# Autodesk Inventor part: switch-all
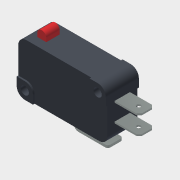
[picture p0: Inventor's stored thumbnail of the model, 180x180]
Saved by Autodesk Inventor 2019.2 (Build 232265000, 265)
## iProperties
Shininess: 64.0
Length Units: 11269
Angle Units: 11279
Time Units: 11290
Mass Units: 11286
Length Display Precision: 3
Angle Display Precision: 2
Compacted: True
Part Number: switch-all
Document SubType Name: Modeling
Created: 2003-07
Designer: garding
Manufacturer: Standard
Standards Organization: Custom
Material: Default
Density: 1 g/cm^3
Appearance: Dark Gray
Density: 0.0
Volumn: 0.0
Area: 0.0
PropertySet Name: Model Information
Control State: 0
Master: False
Checked Out: False
Author: garding
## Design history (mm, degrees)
sketch "Sketch1"
  geometry: L1 (-13.9, 7.95)-(13.9, 7.95); L2 (13.9, 7.95)-(13.9, -7.95); L3 (13.9, -7.95)-(-13.9, -7.95); L4 (-13.9, -7.95)-(-13.9, 7.95); 3 further points
  constraints: 8 end point, 2 midpoint, 2 parallel, 1 horizontal, 1 horizontal alignment, 1 perpendicular, 1 vertical alignment
  dimensions: "d0" = 27.8 distance of L1.start L1.end; "d1" = 15.9 distance of L1.end L2.end
extrude "Extrusion1" new body sketch "Sketch1" stored distance "d2" = 10.3; taper "d3" = 0 deg
fillet "Fillet1" dims "d4" = 2.54
sketch "Sketch2"
  geometry: L1 (0.837, 7.25)-(3.637, 7.25); L2 (3.637, 7.25)-(3.637, 3.05); L3 (3.637, 3.05)-(0.837, 3.05); L4 (0.837, 3.05)-(0.837, 7.25); L5 (0, 0)-(0, 10.3) reference; 2 further points
  constraints: 8 end point, 2 midpoint, 2 parallel, 1 horizontal, 1 horizontal alignment, 1 perpendicular
  dimensions: "d66" = 4.2 distance of L1.end L2.end; "d67" = 2.8 distance of L1.start L1.end
extrude "Extrusion2" join sketch "Sketch2" distance "d5" = 2.54; taper "d6" = 0 deg
fillet "Fillet2" dims "d7" = 1.4
sketch "Sketch3"
  geometry: L1 (-11.36, -7.95)-(11.36, -7.95) reference; L2 (11.754, -10.998)-(1.086, -10.998); L3 (1.086, -10.998)-(1.086, -7.95); L4 (-13.9, 5.41)-(-13.9, -5.41) reference; L5 (11.754, -10.998)-(11.754, -10.236); L6 (11.754, -10.236)-(1.848, -10.236); L7 (1.848, -10.236)-(1.848, -7.95)
  constraints: 10 end point, 2 parallel, 2 perpendicular, 2 point on line
  dimensions: "d10" = 10.668 distance of L2.start L2.end; "d12" = 3.048 distance of L2.end L3.end; "d13" = 14.986 distance between parallel lines of L4 L3; "d14" = 0.762 distance between parallel lines of L2 L6; "d15" = 0.762 distance between parallel lines of L3 L7 (= d14)
extrude "pin1" join sketch "Sketch3" stored distance "d16" = 4.7498; taper "d17" = 0 deg
fillet "pin1 Fillet3" dims "d18" = 0.762, "d19" = 1.524
sketch "Sketch4"
  geometry: L1 (9.144, 0.762)-(9.144, 3.988) reference; 2 further points
  constraints: 1 horizontal alignment, 1 midpoint
hole "pin1 Hole1" sketch "Sketch4" at (6.536, 2.375) diameter "d20" = 1.27; stored, may be unused: countersink angle "d24" = 82 deg, drill point angle "d26" = 118 deg; dims "d21" = 12.7, "d22" = 9.525, "d23" = 6.35, "d25" = 19.05
sketch "Sketch5"
  geometry: A1 r 2.54 centre (-11.36, -5.41) between (-13.9, -5.41) and (-11.36, -7.95) reference; A2 r 2.54 centre (11.36, 5.41) between (13.9, 5.41) and (11.36, 7.95) reference
hole "Hole2" sketch "Sketch5" at (-11.36, -5.41), (11.36, 5.41) diameter "d27" = 2.54; stored, may be unused: countersink angle "d31" = 82 deg, drill point angle "d33" = 118 deg; dims "d28" = 12.7, "d29" = 9.525, "d30" = 6.35, "d32" = 19.05
sketch "Sketch6"
  geometry: L1 (0, 0)-(0, 10.82) reference; L2 (-10.3, 10.82)-(0, 10.82) reference; L3 (-10.3, 10.82)-(-10.3, 0) reference; L4 (-7.525, 8.458)-(-2.775, 8.458); L5 (-2.775, 8.458)-(-2.775, 7.95); L6 (-2.775, 7.95)-(-7.525, 7.95); L7 (-7.525, 7.95)-(-7.525, 8.458); L8 (-10.3, 5.41)-(0, 5.41); 2 further points
  constraints: 10 end point, 4 midpoint, 2 parallel, 1 horizontal, 1 perpendicular, 1 vertical alignment
  dimensions: "d34" = 2.54 distance between parallel lines of L8 L6; "d35" = 0.508 distance of L4.end L5.end; "d36" = 4.7498 distance of L4.start L4.end
extrude "Pin2" join sketch "Sketch6" distance "d37" = 7.62; taper "d38" = 0 deg
chamfer "pin2 Chamfer1" distance "d39" = 0.79375; stored, may be unused: second distance "d40" = 3.175, angle "d41" = 45 deg
sketch "Sketch7"
  geometry: L1 (7.62, 0.794)-(7.62, 3.956) reference; 2 further points
  constraints: 1 horizontal alignment, 1 midpoint
  dimensions: "d42" = 2.54 distance from line of L1 point (5.08, 2.375)
hole "pin2 Hole3" sketch "Sketch7" at (5.08, 2.375) diameter "d43" = 1.27; stored, may be unused: countersink angle "d47" = 82 deg, drill point angle "d49" = 118 deg; dims "d44" = 12.7, "d45" = 9.525, "d46" = 6.35, "d48" = 19.05
sketch "Sketch8"
  geometry: L1 (0, 0)-(0, 10.82) reference; L2 (-10.3, 10.82)-(-10.3, 0) reference; L3 (-2.775, 2.362)-(-7.525, 2.362); L4 (-7.525, 2.362)-(-7.525, 2.87); L5 (-7.525, 2.87)-(-2.775, 2.87); L6 (-2.775, 2.87)-(-2.775, 2.362); L7 (0, 5.41)-(-10.3, 5.41); 2 further points
  constraints: 10 end point, 4 midpoint, 2 parallel, 1 horizontal, 1 perpendicular, 1 vertical alignment
  dimensions: "d50" = 2.54 distance between parallel lines of L7 L5; "d51" = 4.7498 distance of L4.end L5.end; "d52" = 0.508 distance of L5.end L3.start
extrude "pin3" join sketch "Sketch8" distance "d53" = 7.62; taper "d54" = 0 deg
chamfer "c" distance "d55" = 0.79375; stored, may be unused: second distance "d56" = 3.175, angle "d57" = 45 deg
sketch "Sketch9"
  geometry: L1 (7.62, 0.794)-(7.62, 3.956) reference; 2 further points
  constraints: 1 horizontal alignment, 1 midpoint
  dimensions: "d58" = 2.54 distance from line of point (5.08, 2.375) L1
hole "pin3 Hole4" sketch "Sketch9" at (5.08, 2.375) diameter "d59" = 1.27; stored, may be unused: countersink angle "d63" = 82 deg, drill point angle "d65" = 118 deg; dims "d60" = 12.7, "d61" = 9.525, "d62" = 6.35, "d64" = 19.05
sketch "Sketch10"
  geometry: 1 further point
sketch "Sketch13"
  geometry: L1 (11.36, -7.95)-(-11.36, -7.95) reference; L2 (13.9, 5.41)-(13.9, -5.41) reference; L3 (-11.36, 7.95)-(11.36, 7.95) reference; L4 (-13.9, -5.41)-(-13.9, 5.41) reference; L5 (-11.36, -2.87)-(-13.9, -2.87); L6 (-8.82, -5.41)-(-8.82, -7.95); L7 (8.82, 5.41)-(8.82, 7.95); L8 (11.36, 2.87)-(13.9, 2.87); A1 r 2.54 centre (-11.36, -5.41) between (-13.9, -5.41) and (-11.36, -7.95) reference; A2 r 2.54 centre (11.36, -5.41) between (11.36, -7.95) and (13.9, -5.41) reference; A3 r 2.54 centre (11.36, 5.41) between (13.9, 5.41) and (11.36, 7.95) reference; A4 r 2.54 centre (-11.36, 5.41) between (-11.36, 7.95) and (-13.9, 5.41) reference; A5 r 2.54 centre (-11.36, -5.41) between (-8.82, -5.41) and (-11.36, -2.87); A6 r 2.54 centre (11.36, 5.41) between (8.82, 5.41) and (11.36, 2.87)
  constraints: 11 end point, 5 point on circle, 4 point on line, 4 tangent, 3 perpendicular, 2 centre point, 2 coincident, 1 parallel
extrude "Extrusion6" cut sketch "Sketch13" distance "d68" = 0.5; taper "d69" = 0 deg
sketch "Sketch14"
  geometry: L1 (-13.9, 2.87)-(-13.9, -5.41) reference; L2 (-13.9, 2.87)-(-11.36, 2.87) reference; L3 (-8.82, 5.41)-(-8.82, 7.95) reference; L4 (11.36, 7.95)-(-8.82, 7.95) reference; L5 (13.9, -2.87)-(13.9, 5.41) reference; L6 (13.9, -2.87)-(11.36, -2.87) reference; L7 (8.82, -5.41)-(8.82, -7.95) reference; L8 (-11.36, -7.95)-(8.82, -7.95) reference; A1 r 2.54 centre (-11.36, 5.41) between (-11.36, 2.87) and (-8.82, 5.41) reference; A2 r 2.54 centre (11.36, 5.41) between (13.9, 5.41) and (11.36, 7.95) reference; A3 r 2.54 centre (11.36, -5.41) between (11.36, -2.87) and (8.82, -5.41) reference; A4 r 2.54 centre (-11.36, -5.41) between (-13.9, -5.41) and (-11.36, -7.95) reference
extrude "Extrusion7" cut sketch "Sketch14" distance "d70" = 0.5; taper "d71" = 0 deg
body "Solid1"
node "Projected Loop1"
